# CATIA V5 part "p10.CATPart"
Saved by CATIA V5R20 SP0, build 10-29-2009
Part number: p10
Publications: "Line.4", "Line.5", "Point.3", "Plane.2", "Plane.3", "Plane.4"
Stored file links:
  D:\Dropbox\IAO_2011\MMS_GR2\IAO_2011_1439_jlicbarski\p10.CATPart
  D:\Dropbox\IAO_2011\MMS_GR2\IAO_2011_1439_jlicbarski\train.CATProduct

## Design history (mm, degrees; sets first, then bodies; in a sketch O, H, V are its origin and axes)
AxisSystem1: origin (0, 0, 0), X (1, 0, 0), Y (0, 1, 0), Z (0, 0, 1)
Set1
  Point1: linked copy from another document
  Point2: linked copy from another document
Body1 (main body)
  Line1: type PtDir, RefPoint Point1, Direction edge [XY plane of AxisSystem1 | ZX plane of AxisSystem1], Start 0, End 15
  Line2: type PtPt, FirstPoint Point2, SecondPoint Point1
  Point3: type OnCurve, Support Line1, Length 2.5
  Plane1: type Normal, Curve Line1, RefPoint Point3
  Plane2: type Normal, Curve Line1, RefPoint Point1
  Plane3: type Normal, Curve Line2, RefPoint Point1
  Sketch1 on Plane2, origin (-12.5, 0, 0), H (0, 1, 0), V (0, 0, 1)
